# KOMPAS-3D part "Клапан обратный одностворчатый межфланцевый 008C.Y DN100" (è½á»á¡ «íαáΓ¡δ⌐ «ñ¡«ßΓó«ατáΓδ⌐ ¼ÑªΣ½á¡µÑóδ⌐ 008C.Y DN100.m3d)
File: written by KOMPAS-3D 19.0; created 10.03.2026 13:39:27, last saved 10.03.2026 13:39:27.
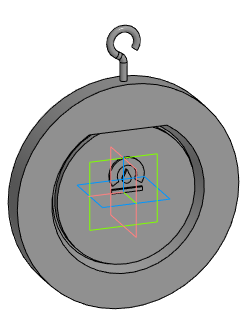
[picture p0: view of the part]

Document properties: Автор: Евгений; Полное имя файла: E:\Dendor\3D для проектировщиков\5.1 Тип 008C. Клапан обратный одностворчатый межфланцевый\stp_Клапан обратный одностворчатый межфланцевый 008C.Y\Клапан обратный одностворчатый межфланцевый 008C.Y DN100.m3d

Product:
- Part/product: Клапан обратный одностворчатый межфланцевый 008C.Y DN100

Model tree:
1. Операция без истории:1  (labels: Клапан обратный одностворчатый межфланцевый 008C.Y DN100)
